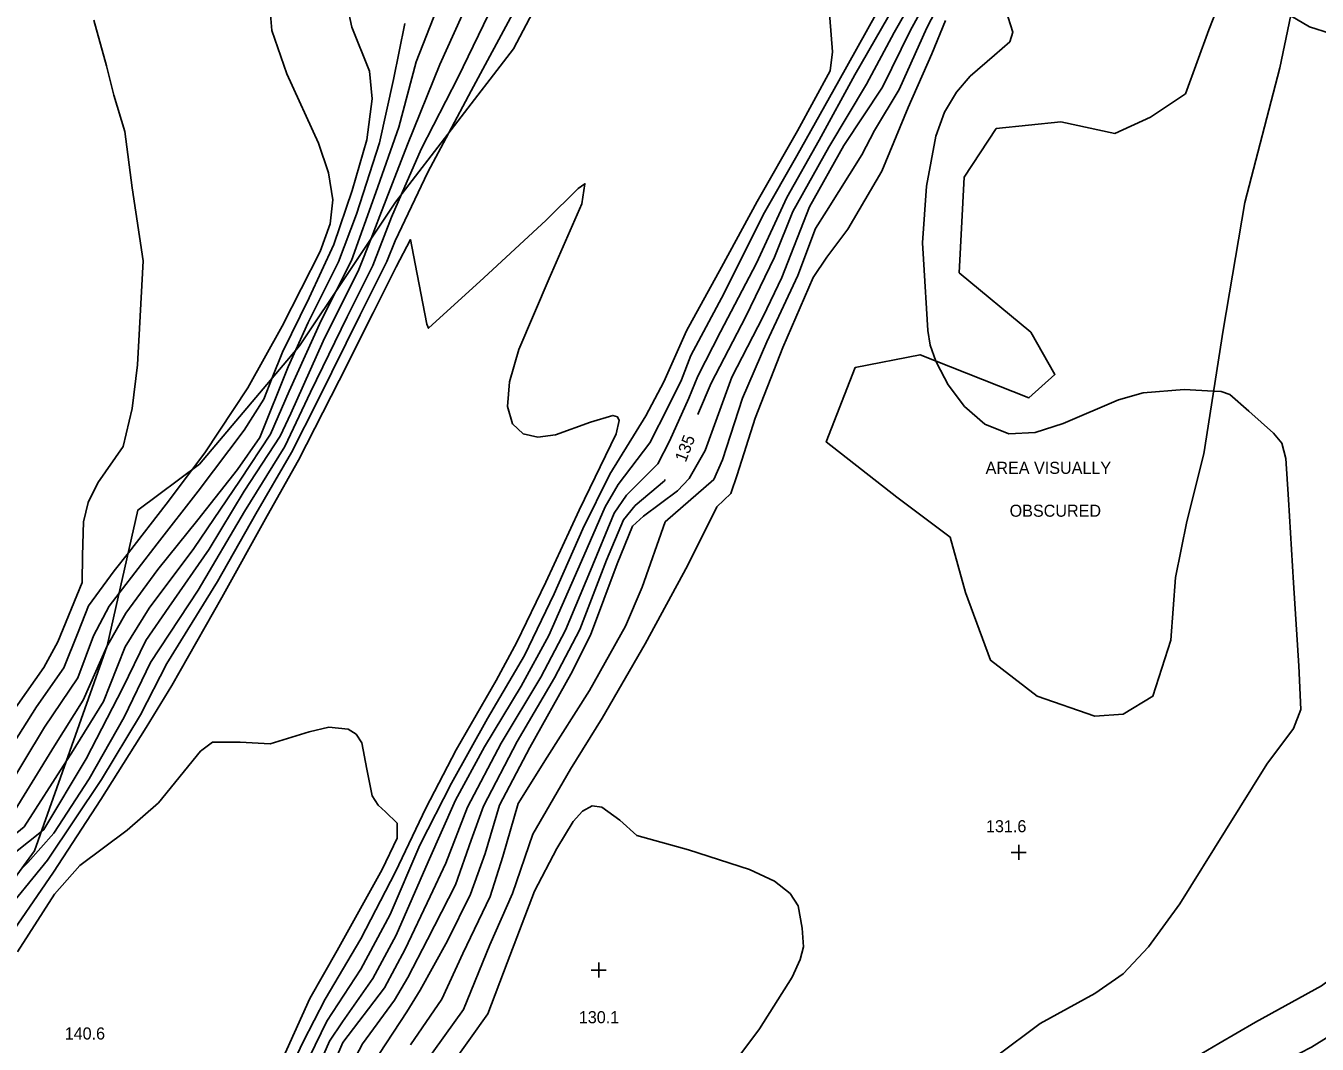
# Model space of a CAD drawing. Extents: x 1467615 to 2003689, y 770235 to 1108726.
# Drawn here: x 2002136.4 to 2002350.5, y 771017.7 to 771186.6 of the extents above; entities that cross this region are included whole.
import ezdxf

# ---------------------------------------------------------------- set-up
doc = ezdxf.new("R2010")
doc.units = 0
for name, color, linetype in [('RD_DTM_Major1', 7, 'Continuous'), ('RD_DTM_Major1_Lbl', 7, 'Continuous'), ('RD_DTM_Major2', 7, 'Continuous'), ('RD_DTM_Minor1', 7, 'Continuous'), ('RD_DTM_Minor2', 7, 'Continuous'), ('RD_DTM_Obscure', 7, 'Continuous'), ('RD_DTM_Spot_Elev', 7, 'Continuous'), ('RD_TX_Misc1', 7, 'Continuous')]:
    doc.layers.add(name, color=color, linetype=linetype)

msp = doc.modelspace()

# ---------------------------------------------------------------- linework, layer by layer
at = {"layer": 'RD_DTM_Major1'}
for points in [[(2002247.87, 771122.14), (2002247.97, 771122.38), (2002250.07, 771127.32), (2002255.82, 771138.4), (2002260.57, 771148.19), (2002263.62, 771155.77), (2002269.56, 771166.44), (2002275.82, 771176.87), (2002280.38, 771185.46), (2002286.53, 771196.24), (2002293, 771208.43), (2002297.86, 771216.63), (2002302.88, 771224.43), (2002308.03, 771231.08), (2002315.38, 771241.58), (2002318.55, 771246.47), (2002323.15, 771254.74), (2002330.92, 771262.48), (2002334.58, 771265.97), (2002336.61, 771268.06), (2002337.5, 771269.94), (2002338.11, 771271.89), (2002339.11, 771272.06), (2002344.06, 771272.22)], [(2002187.86, 771142.62), (2002185.39, 771137.7), (2002180.1, 771126.01), (2002177.01, 771118.89), (2002171.98, 771111.26), (2002164.27, 771099.92), (2002156.85, 771090.01), (2002152.89, 771083.6), (2002150.34, 771077.22), (2002149.27, 771074.58), (2002144, 771066), (2002143.16, 771064.7)], [(2002158.93, 770952.97), (2002161.96, 770960.03), (2002164.53, 770964.16), (2002170.64, 770971.26), (2002174.19, 770980.5), (2002177.29, 770987.25), (2002183.77, 770996.78), (2002186.54, 771001.38), (2002189.58, 771012.75), (2002192.22, 771017.78), (2002197.56, 771025.02), (2002199.73, 771028.81), (2002203.02, 771035.11), (2002207.68, 771044.17), (2002210.25, 771051.55), (2002212.3, 771057.18), (2002217.91, 771067.91), (2002224.06, 771078.47), (2002228.26, 771086.51), (2002232.7, 771098), (2002235.49, 771104.66), (2002237.44, 771107.03), (2002242.29, 771111.13), (2002242.45, 771111.37)], [(2002178.44, 771014.07), (2002183.53, 771025.31), (2002188.05, 771033.28), (2002195.51, 771046.69), (2002197.97, 771051.9), (2002198, 771054.37), (2002196.06, 771056.28), (2002194.84, 771057.39), (2002193.84, 771058.91), (2002192.95, 771063.34), (2002192.13, 771067.71), (2002191.19, 771069.12), (2002189.89, 771069.96), (2002186.68, 771070.29), (2002183.39, 771069.51), (2002176.95, 771067.53), (2002171.96, 771067.83), (2002167.35, 771067.8), (2002165.37, 771066.3), (2002158.39, 771057.77), (2002153.24, 771053.23), (2002145.35, 771047.35), (2002141.19, 771042.6), (2002135.05, 771033.08)]]:
    msp.add_lwpolyline(points, dxfattribs=at)
at = {"layer": 'RD_DTM_Major2'}
for points in [[(2002204.55, 771189.34), (2002201.14, 771180.62), (2002198.27, 771169.77), (2002194.43, 771158.93), (2002190.39, 771147.68), (2002187.86, 771142.62)], [(2002143.16, 771064.7), (2002136.14, 771053.79), (2002126.52, 771045.96), (2002125.07, 771044.03), (2002123.4, 771038.62), (2002119.48, 771027.09)]]:
    msp.add_lwpolyline(points, dxfattribs=at)
at = {"layer": 'RD_DTM_Minor1'}
for points in [[(2002186.72, 771012.79), (2002188.99, 771018.05), (2002195.9, 771027.08), (2002199.29, 771033.49), (2002203.48, 771042.21), (2002206.08, 771047.78), (2002209.66, 771057.03), (2002215.21, 771067.62), (2002221.8, 771078.61), (2002225.91, 771086.4), (2002230.02, 771096.29), (2002233.99, 771105.75), (2002236.04, 771108.77), (2002241.23, 771113.96), (2002243.16, 771117.72), (2002246.33, 771124.83), (2002247.87, 771128.49), (2002251.59, 771135.83), (2002257.58, 771147.22), (2002262.59, 771158.13), (2002267.97, 771167.61), (2002273.85, 771178.44), (2002278.29, 771186.11), (2002285.45, 771198.53)], [(2002192.72, 771012.64), (2002199.59, 771023.09), (2002201.8, 771026.68), (2002206.35, 771034.87), (2002210.16, 771042.62), (2002212.58, 771049.36), (2002214.94, 771057.34), (2002219.98, 771066.91), (2002226.79, 771079.11), (2002230.07, 771085.53), (2002234.47, 771097.4), (2002237, 771103.6), (2002238.84, 771105.3), (2002244.49, 771109.5), (2002246.38, 771111.51), (2002249.04, 771116.18), (2002253.46, 771128.3), (2002258.65, 771138.39), (2002261.76, 771144.85), (2002266.35, 771156.55), (2002272.04, 771166.71), (2002278.48, 771176.37), (2002283.09, 771185.84), (2002289.41, 771197.29)], [(2002200.21, 771017.62), (2002205.37, 771025.22), (2002208.9, 771032.79), (2002213.39, 771042.2), (2002215.52, 771048.85), (2002218.04, 771057.65), (2002222.88, 771065.35), (2002229.87, 771076.38), (2002235.85, 771087.02), (2002238.61, 771093.52), (2002242.41, 771104.33), (2002250.47, 771111.36), (2002251.92, 771114.6), (2002255.24, 771124.81), (2002259.28, 771134.15), (2002264.41, 771145.17), (2002267.34, 771152.97), (2002269.2, 771155.81), (2002275.02, 771165.18), (2002277.14, 771169.21), (2002281.23, 771176.02), (2002285.79, 771186.22), (2002290.72, 771195.75)], [(2002183.44, 771015.67), (2002186.33, 771021.54), (2002191.98, 771030.2), (2002196.82, 771039.22), (2002201.74, 771050.72), (2002206.97, 771061.01), (2002212.96, 771071.73), (2002219.1, 771082.17), (2002224.04, 771092.39), (2002228.77, 771103.16), (2002233.24, 771112.23), (2002239.23, 771121.9), (2002242.18, 771127.55), (2002245.97, 771135.98), (2002251.74, 771146.53), (2002257.7, 771157.42), (2002264.37, 771169.14), (2002269.76, 771179.11), (2002270.19, 771182.25), (2002269.37, 771192.84)], [(2002298.51, 771190.4), (2002300.1, 771185.49), (2002299.57, 771183.92), (2002297.06, 771181.72), (2002292.98, 771178.2), (2002290.73, 771175.56), (2002288.76, 771172.25), (2002287.32, 771168.28), (2002285.75, 771159.99), (2002285.07, 771150.6), (2002285.28, 771147.9), (2002285.96, 771136.03), (2002286.39, 771133.64), (2002287.32, 771130.99)], [(2002182.71, 771009), (2002186.77, 771018.22), (2002188.9, 771021.44), (2002193.94, 771028.64), (2002197.8, 771035.84), (2002203.12, 771047.99), (2002207.68, 771058.22), (2002212.45, 771067.04), (2002218.55, 771077.11), (2002223.11, 771085.49), (2002228.58, 771097.83), (2002232.49, 771106.84), (2002234.64, 771110.5), (2002239.9, 771117.46), (2002242.9, 771123.39), (2002245.14, 771127.87), (2002246.67, 771131.92), (2002252.23, 771142.26), (2002258.69, 771155.21), (2002264.27, 771165.02), (2002271.21, 771177.42), (2002277.37, 771188.42)], [(2002202.53, 771014.51), (2002208.97, 771023.49), (2002213.38, 771034.2), (2002217.1, 771042.73), (2002220.47, 771052.55), (2002226.74, 771063.35), (2002231.97, 771071.78), (2002239.11, 771084.11), (2002246.21, 771097.17), (2002251.01, 771106.8), (2002253.29, 771109.06), (2002254.37, 771112.11), (2002257.35, 771121.52), (2002261.92, 771133.24), (2002266.98, 771144.86), (2002269.23, 771148.21), (2002272.7, 771152.86), (2002278.37, 771162.47), (2002282.73, 771173), (2002286.66, 771181.93), (2002288.91, 771187.42)], [(2002346.15, 771188.23), (2002349.24, 771186.4), (2002352.73, 771185.28), (2002358.73, 771185.06), (2002371.37, 771186.57), (2002373.65, 771186.36), (2002375.57, 771185.44), (2002378.41, 771182.8), (2002380.99, 771179.47), (2002382.07, 771175.83), (2002382.31, 771170.22), (2002382.31, 771170.08)], [(2002206.56, 771168.85), (2002203.07, 771162.32), (2002197.66, 771150.94), (2002196.26, 771147.47), (2002191.85, 771138.66), (2002184.83, 771124.45), (2002180.49, 771115.82), (2002174.57, 771105.67), (2002168.19, 771094.46), (2002159.78, 771080.85), (2002155.43, 771072.36), (2002148.94, 771061.63), (2002140, 771048.24), (2002131.96, 771038.4)], [(2002177.14, 771007.01), (2002182.4, 771018.13), (2002186.06, 771025.18), (2002191.96, 771035.19), (2002197.72, 771046.29), (2002202.73, 771056.88), (2002207.77, 771066.54), (2002214.43, 771078.06), (2002217.85, 771084.4), (2002222.63, 771094.35), (2002228.19, 771106.28), (2002234.31, 771118.9), (2002234.78, 771121.16), (2002234.5, 771121.75), (2002233.73, 771121.99), (2002230.02, 771120.86), (2002224.22, 771118.75), (2002221.34, 771118.36), (2002218.89, 771118.92), (2002217.12, 771120.58), (2002216.28, 771123.43), (2002216.59, 771127.56), (2002218.16, 771132.92), (2002223.18, 771144.65), (2002228.6, 771157.03), (2002229.13, 771160.37), (2002228.01, 771159.62), (2002222.7, 771154.36), (2002212.36, 771144.79), (2002203.16, 771136.44), (2002202.9, 771137.11), (2002200.99, 771147.11), (2002200.19, 771151.13), (2002197.8, 771146.6), (2002194, 771138.98), (2002188.39, 771127.74), (2002181.64, 771114.56), (2002176.45, 771105.31), (2002168.89, 771091.79), (2002160.63, 771077.19), (2002156.35, 771070.22), (2002148.84, 771058.28), (2002141.01, 771046.26), (2002132.43, 771033.79)], [(2002198.73, 771158.65), (2002197.06, 771154.83), (2002193.96, 771146.82), (2002189.69, 771138.34), (2002183.6, 771125.85), (2002179.35, 771116.83), (2002172.68, 771106.03), (2002164.98, 771093.02), (2002157.07, 771081), (2002152.7, 771071.94), (2002146.91, 771061.74), (2002141.06, 771052.75), (2002136.76, 771047.89), (2002135.68, 771046.8)], [(2002193.65, 771151.28), (2002191.66, 771146.16), (2002185.71, 771134.31), (2002180.33, 771122.3), (2002178.6, 771118.55), (2002172.64, 771109.4), (2002166.79, 771099.81), (2002160.13, 771090.18), (2002156.3, 771084.64), (2002152.48, 771076.83), (2002146.41, 771065.03), (2002139.41, 771053.33), (2002139.02, 771053.01)], [(2002181.19, 771132.84), (2002179.92, 771130.03), (2002175.22, 771118.33), (2002171.51, 771113.02), (2002164.93, 771104.67), (2002158.32, 771096.44), (2002152.99, 771089.2), (2002150.01, 771083.94), (2002149.93, 771083.77)], [(2002177.28, 771128.21), (2002175.86, 771124.67), (2002172.62, 771119.54), (2002164.99, 771109.42), (2002158.17, 771100.68), (2002151.91, 771092.53)], [(2002333.37, 771126.02), (2002334.61, 771125.95), (2002336.03, 771125.43), (2002339.19, 771122.7), (2002343.28, 771119.05), (2002344.67, 771117.38), (2002345.36, 771114.85), (2002345.77, 771108.02), (2002346.62, 771094.24), (2002347.47, 771080.46), (2002347.82, 771073.23), (2002346.62, 771070.05), (2002342.18, 771064.17), (2002335.36, 771053.18), (2002327.75, 771040.99), (2002322.59, 771033.86), (2002318.38, 771029.39), (2002313.68, 771026.12), (2002304.63, 771021.18), (2002297.38, 771015.78)], [(2002388.51, 771115.68), (2002390.27, 771107.93), (2002393.12, 771098.76), (2002396.2, 771092.03), (2002399.64, 771086.51), (2002402.86, 771082.85), (2002404.25, 771080.35), (2002404.25, 771077.56), (2002403.97, 771074.22), (2002402.66, 771072.4), (2002400.04, 771069.59), (2002389.75, 771061.83), (2002377.56, 771052.89), (2002372.08, 771048.25), (2002368.36, 771043.97), (2002363.21, 771037.19), (2002358.02, 771032.38), (2002351.23, 771027.39), (2002340.31, 771021.4), (2002334.23, 771017.87), (2002324.82, 771012.31), (2002317.66, 771007.73)], [(2002164.06, 771113.05), (2002159.71, 771107.24), (2002153.42, 771099.22)], [(2002213.01, 771022.79), (2002216.25, 771031.22), (2002220.78, 771043.13), (2002224.44, 771050.21), (2002227.19, 771054.65), (2002228.72, 771056.35), (2002230.32, 771057.23), (2002231.95, 771057.06), (2002234.89, 771054.88), (2002237.74, 771052.35), (2002246.32, 771049.97), (2002256.41, 771046.72), (2002260.55, 771044.77), (2002263.15, 771042.72), (2002264.47, 771040.67), (2002265.15, 771036.99), (2002265.34, 771033.87), (2002264.82, 771031.8), (2002263.47, 771028.87), (2002258.04, 771020.3), (2002252, 771012.18)], [(2002362.2, 771025.11), (2002349.57, 771017.23), (2002339.92, 771012.27), (2002333.46, 771009.74), (2002330.4, 771008.7), (2002323.66, 771005.57), (2002318.28, 771001.91)], [(2002206.71, 771013.94), (2002213.01, 771022.79)]]:
    msp.add_lwpolyline(points, dxfattribs=at)
at = {"layer": 'RD_DTM_Minor2'}
for points in [[(2002313.78, 771333.52), (2002307.9, 771328.09), (2002301.52, 771321.41), (2002294.72, 771313.39), (2002284.25, 771301.3), (2002275.23, 771291.54), (2002269.34, 771283.9), (2002266.14, 771278.6), (2002261.86, 771268.53), (2002257.94, 771262.3), (2002250.83, 771253.06), (2002241.72, 771242.24), (2002233.85, 771233.78), (2002229.88, 771228.1), (2002222.77, 771215.81), (2002215.91, 771202.9), (2002211.17, 771193.64), (2002205.08, 771180.17), (2002199.69, 771166.89), (2002195.13, 771155.06), (2002193.65, 771151.28)], [(2002244.45, 771239.43), (2002241.07, 771235.53), (2002237.45, 771231.16), (2002232.84, 771223.55), (2002225.52, 771211.4), (2002218.44, 771199.62), (2002213.98, 771190.17), (2002208.1, 771178.05), (2002201.97, 771166.09), (2002198.73, 771158.65)], [(2002236.14, 771220.58), (2002236, 771220.37), (2002227.36, 771207.4), (2002223.07, 771200.33), (2002217.53, 771189.32), (2002210.27, 771175.78), (2002206.56, 771168.85)], [(2002176.85, 771189.74), (2002177.2, 771185.78), (2002179.72, 771178.61), (2002184.95, 771167.12), (2002186.6, 771162.18), (2002187.32, 771157.74), (2002186.9, 771153.73), (2002185.21, 771149.14), (2002178.94, 771136.77), (2002173.2, 771126.55), (2002166.11, 771115.8), (2002164.06, 771113.05)], [(2002189.78, 771189.64), (2002190.46, 771186.33), (2002193.4, 771179.06), (2002193.87, 771174.46), (2002192.96, 771167.66), (2002190.53, 771159.29), (2002187.5, 771150.29), (2002183.37, 771141.46), (2002178.97, 771132.45), (2002177.28, 771128.21)], [(2002147.69, 771187.48), (2002149.8, 771179.93), (2002151.01, 771175.09), (2002152.83, 771169.05), (2002154.04, 771159.68), (2002155.85, 771147.59), (2002155.24, 771136.4), (2002154.94, 771130.36), (2002154.04, 771123.11), (2002152.55, 771116.8), (2002148.33, 771110.79), (2002146.78, 771107.54), (2002145.97, 771104.36), (2002145.81, 771098.78), (2002145.74, 771094.27), (2002141.73, 771084.45), (2002139.41, 771080.2), (2002132.2, 771069.96), (2002126.68, 771060.62), (2002119.79, 771050.25), (2002116.89, 771044.1), (2002113.47, 771033.61), (2002109.26, 771023.92), (2002107.11, 771020.03)], [(2002199.24, 771186.94), (2002197.39, 771177.64), (2002195.08, 771167.15), (2002191.26, 771155.33), (2002188.28, 771147.42), (2002183.24, 771137.38), (2002181.19, 771132.84)], [(2002287.32, 771130.99), (2002287.45, 771130.63), (2002289.37, 771127.06), (2002292.07, 771123.46), (2002295.45, 771120.53), (2002299.41, 771118.94), (2002303.8, 771119.14), (2002308.43, 771120.63), (2002317.57, 771124.56), (2002321.68, 771125.71), (2002328.46, 771126.3), (2002333.37, 771126.02)], [(2002153.42, 771099.22), (2002151.08, 771096.24), (2002146.82, 771090.43), (2002145.11, 771086.02), (2002142.71, 771080.11), (2002138.18, 771073.68), (2002133.66, 771066.5), (2002126.94, 771055.66), (2002120.68, 771047.93), (2002118.58, 771043.03), (2002115.37, 771033.07), (2002110.82, 771022), (2002110.23, 771020.92)], [(2002151.91, 771092.53), (2002150.23, 771090.34), (2002147.66, 771085.42), (2002145.04, 771078.48), (2002139.54, 771070.32), (2002132.83, 771059.21), (2002130.01, 771055.04), (2002121.87, 771046.13), (2002120.42, 771042.36), (2002116.94, 771031.63), (2002113.47, 771023.08)], [(2002149.93, 771083.77), (2002145.92, 771074.79), (2002141.17, 771067.19), (2002133.78, 771055.17), (2002130.7, 771052.32), (2002124.53, 771046.87), (2002123.14, 771044.35), (2002121.33, 771038.54), (2002117.83, 771028.28), (2002116.45, 771025.07)], [(2002139.02, 771053.01), (2002130.88, 771046.58), (2002127.06, 771043.15), (2002126.04, 771040.53), (2002122.57, 771029.48), (2002122.39, 771029.03)]]:
    msp.add_lwpolyline(points, dxfattribs=at)
at = {"layer": 'RD_DTM_Obscure'}
for points in [[(2002122.96, 771029.4), (2002137.88, 771049.81), (2002149.93, 771083.76), (2002155.01, 771106.28), (2002165.19, 771113.9), (2002181.77, 771133.53), (2002197.7, 771157.31), (2002217.27, 771182.77), (2002230.57, 771207.93)], [(2002291.18, 771145.62), (2002291.99, 771161.47), (2002297.32, 771169.52), (2002308.02, 771170.67), (2002317, 771168.72), (2002322.9, 771171.41), (2002328.7, 771175.3), (2002332.55, 771185.91), (2002337.54, 771198.59)], [(2002346.96, 771192.08), (2002344.35, 771179.61), (2002338.53, 771157.25), (2002334.96, 771136.09), (2002331.73, 771115.59), (2002328.92, 771104.4), (2002327.03, 771095.11), (2002326.25, 771084.74), (2002323.28, 771075.43), (2002318.34, 771072.46), (2002313.69, 771072.12), (2002304.1, 771075.41), (2002296.39, 771081.4), (2002292.23, 771092.63), (2002289.68, 771101.77), (2002280.84, 771108.44), (2002269.14, 771117.58), (2002273.91, 771129.91), (2002284.69, 771132.04), (2002302.73, 771124.87), (2002307.06, 771128.77), (2002303.06, 771135.76), (2002291.18, 771145.62)]]:
    msp.add_lwpolyline(points, dxfattribs=at)
at = {"layer": 'RD_DTM_Spot_Elev'}
for p, q in [((2002299.8, 771049.53), (2002302.3, 771049.53)), ((2002301.05, 771048.28), (2002301.05, 771050.78)), ((2002231.4, 771028.79), (2002231.4, 771031.29)), ((2002230.15, 771030.04), (2002232.65, 771030.04))]:
    msp.add_line(p, q, dxfattribs=at)

# ---------------------------------------------------------------- texts
at = {"layer": 'RD_DTM_Major1_Lbl'}
msp.add_text('135', height=2, rotation=68.8623, dxfattribs=at).set_placement((2002245.83, 771114.09))
at = {"layer": 'RD_DTM_Spot_Elev'}
for s, p in [('131.6', (2002295.62, 771052.88)), ('130.1', (2002228.11, 771021.22)), ('140.6', (2002142.86, 771018.52))]:
    msp.add_text(s, height=2, dxfattribs=at).set_placement(p)
at = {"layer": 'RD_TX_Misc1'}
for s, p in [('AREA VISUALLY', (2002295.56, 771112.29)), ('OBSCURED', (2002299.54, 771105.18))]:
    msp.add_text(s, height=2, dxfattribs=at).set_placement(p)

doc.saveas('drawing.dxf')
